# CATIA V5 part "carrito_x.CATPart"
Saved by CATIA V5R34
Part number: Part6
Bounding box of the stored display mesh (mm): x -30 to 30, y 0 to 70, z 0 to 11
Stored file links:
  C:\Users\Apolinar\Desktop\cnc\carrito_x.CATPart
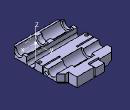
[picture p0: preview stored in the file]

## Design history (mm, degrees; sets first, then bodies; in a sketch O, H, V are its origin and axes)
AxisSystem1: origin (0, 0, 0), X (1, 0, 0), Y (0, 1, 0), Z (0, 0, 1)
Body1 (main body)
  Sketch1 on XY plane of AxisSystem1, origin (0, 0, 0), H (1, 0, 0), V (0, 1, 0)
    line L1 (-30, 70) -> (30, 70)
    line L2 (30, 70) -> (30, 0)
    line L3 (30, 0) -> (-30, 0)
    line L4 (-30, 0) -> (-30, 70)
    point P3 (30, 0)
    length L1 = 60
    length L2 = 70
    distance V L2 = 30
    horizontal: L1 H, L3 H
    vertical: L2 V, L4 V
    coincidence: P3 H
  Pad1: profile Sketch1, direction (0, 0, 1), length 11
  Sketch2 on end face of Pad1, origin (0, 0, 11), H (1, 0, 0), V (0, 1, 0)
    line L1 (-27, 18.35) -> (-3, 18.35)
    line L2 (-3, 18.35) -> (-3, 2.35)
    line L3 (-3, 2.35) -> (-27, 2.35)
    line L4 (-27, 2.35) -> (-27, 18.35)
    line L5 (3, 18.35) -> (27, 18.35)
    line L6 (27, 18.35) -> (27, 2.35)
    line L7 (27, 2.35) -> (3, 2.35)
    line L8 (3, 2.35) -> (3, 18.35)
    line L9 (-12, 58.35) -> (12, 58.35)
    line L10 (12, 58.35) -> (12, 42.35)
    line L11 (12, 42.35) -> (-12, 42.35)
    line L12 (-12, 42.35) -> (-12, 58.35)
    reference projected line E1 (-30, 70) -> (-30, 0) from edge [face of Pad1 from Sketch1.L4 | end face of Pad1]
    reference projected line E2 (30, 0) -> (30, 70) from edge [face of Pad1 from Sketch1.L2 | end face of Pad1]
    construction line L13 (-27, 10.35) -> (3, 10.35)
    point P13 (-27, 10.35)
    point P14 (3, 10.35)
    construction line L14 (-12, 50.35) -> (-4.1097, 50.35)
    point P15 (-12, 50.35)
    reference projected line E3 (-30, 0) -> (30, 0) from edge [face of Pad1 from Sketch1.L3 | end face of Pad1]
    axis line L15 (0, 52.893) -> (0, 58.35)
    point P17 (0, 58.35)
    length L9 = 24
    length L10 = 16
    length L4 = 16
    length L1 = 24
    length L5 = 24
    distance E1 L4 = 3
    distance L6 E2 = 3
    distance L13 L14 = 40
    distance L3 E3 = 2.35
    horizontal: L1 H, L3 H, L5 H, L7 H, L9 H, L11 H, L13 H, L14 H
    vertical: L2 V, L4 V, L6 V, L8 V, L10 V, L12 V, L15 V
    coincidence: L3 L7, P17 L9, L15 V
    midpoint: P15 L12, P13 L4, P14 L8, P17 L9
  Pocket1: profile Sketch2, direction (0, 0, -1), length 7.6
  Fillet1: radius 7.5, on edge [face of Pocket1 from Sketch2.L9 | end face of Pocket1]; edge [face of Pocket1 from Sketch2.L11 | end face of Pocket1]; edge [face of Pocket1 from Sketch2.L5 | end face of Pocket1]; edge [face of Pocket1 from Sketch2.L1 | end face of Pocket1]; edge [face of Pocket1 from Sketch2.L7 | end face of Pocket1]; edge [face of Pocket1 from Sketch2.L3 | end face of Pocket1]
  Sketch3 on face of Pad1 from Sketch1.L4, origin (-30, 0, 0), H (0, -1, 0), V (0, 0, 1)
    circle A1 centre (-49.85, 10.9) radius 5
    circle A2 centre (-9.85, 10.9) radius 5
    axis line L1 (-49.85, 10.9) -> (-9.85, 10.9)
    reference projected point E1 (-49.85, 10.9) from axis of face of Fillet1
    reference projected point E2 (-9.85, 10.9) from axis of face of Fillet1
    radius A1 = 5
    radius A2 = 5
    concentricity: A1 E1, A2 E2
  Pocket2: profile Sketch3, direction (1, 0, 0), through (limit type 3)
  Sketch4 on end face of Pad1, origin (0, 0, 11), H (1, 0, 0), V (0, 1, 0)
    circle A1 centre (-27.5, 32.851) radius 1.75
    point P1 (-27.5, 32.851)
    reference projected point E1 (-30, 44.851) from vertex [face of Pad1 from Sketch1.L4 | face of Pocket2 from Sketch3.A1 | end face of Pad1]
    circle A2 centre (27.5, 32.851) radius 1.75
    radius A1 = 1.75
    distance P1 V = 27.5
    distance E1 P1 V = 12
    symmetry: A1 A2 V
  Pocket3: profile Sketch4, direction (0, 0, -1), through (limit type 3)
  Sketch5 on end face of Pad1, origin (0, 0, 11), H (1, 0, 0), V (0, 1, 0)
    reference projected line E1 through (0, 9.85) direction (-1, 0) from axis of face of Fillet1
    reference projected line E2 through (0, 49.85) direction (-1, 0) from axis of face of Pocket2 from Sketch3.A1
    construction line L1 (30, 22.85) -> (30, 38.85)
    point P2 (30, 38.85)
    construction line L2 (21.2764, 30.85) -> (30, 30.85)
    point P4 (30, 30.85)
    reference projected line E3 (30, 0) -> (30, 70) from edge [face of Pad1 from Sketch1.L2 | end face of Pad1]
    axis line L3 (30, 38.85) -> (-20.2179, 38.85)
    point P5 (-20.2179, 38.85)
    point P6 (-20.2179, 22.85)
    point P7 (30, 22.85)
    construction line L4 (30, 22.85) -> (-20.2179, 22.85)
    point P8 (-30, 39.7)
    line L5 (-30, 39.7) -> (-10, 39.7)
    line L6 (-10, 39.7) -> (-10, 38.2)
    line L7 (-10, 38.2) -> (-30, 38.2)
    line L8 (-30, 38.2) -> (-30, 39.7)
    point P9 (-10, 39.7)
    point P10 (-10, 38.2)
    point P11 (-30, 38.2)
    reference projected line E4 (-30, 70) -> (-30, 0) from edge [face of Pad1 from Sketch1.L4 | end face of Pad1]
    reference projected line E5 through (0, 10.85) direction (1, 0) from axis of face of Fillet1
    point P12 (20.2179, 38.85)
    point P13 (30, 39.7)
    point P14 (10, 39.7)
    point P15 (10, 38.2)
    point P16 (30, 38.2)
    line L9 (30, 39.7) -> (10, 39.7)
    line L10 (10, 39.7) -> (10, 38.2)
    line L11 (10, 38.2) -> (30, 38.2)
    line L12 (30, 38.2) -> (30, 39.7)
    line L13 (-30, 29.5) -> (30, 29.5)
    line L14 (30, 29.5) -> (30, 19.5)
    line L15 (30, 19.5) -> (-30, 19.5)
    line L16 (-30, 19.5) -> (-30, 29.5)
    distance E1 E2 = 40 (reference)
    length L1 = 16
    length L8 = 1.5
    distance L7 L3 = 0.65
    length L7 = 20
    distance L2 E5 = 20
    length L14 = 10
    distance L15 H = 19.5
    vertical: L1 V, L6 V, L8 V, L14 V, L16 V
    horizontal: L2 H, L3 H, L5 H, L7 H, L13 H, L15 H
    midpoint: P4 L1
    coincidence: L1 E3, L8 E4, L16 E4, E3 L14
    symmetry: P5 P6 L2, P2 P7 L2, L3 L4 L2, P5 P12 V, P8 P13 V, P9 P14 V, P10 P15 V, P11 P16 V, L5 L9 V, L6 L10 V, L7 L11 V, L8 L12 V
  Pocket4: profile Sketch5, direction (0, 0, -1), length 8
  Plane1: type Angle, RefPlane ZX plane of AxisSystem1, Direction edge [ZX plane of AxisSystem1 | YZ plane of AxisSystem1], Angle 45
  Sketch6 on Plane1, origin (0, 0, 0), H (-0.7071, -0.7071, 0), V (0, 0, 1)
    circle A1 centre (-9.3589, 6) radius 1.5
    reference projected point E1 (-6.8589, 3) from vertex [face of Pocket4 from Sketch5.L5 | end face of Pocket4 | face of Pad1 from Sketch1.L4]
    reference projected line E2 (-6.8589, 11) -> (-6.8589, 3) from edge [face of Pad1 from Sketch1.L4 | face of Pocket4 from Sketch5.L5]
    radius A1 = 1.5
    distance A1 E1 V = 1.5
    distance A1 E2 = 1
  Pocket5: profile Sketch6, direction (-0.7071, 0.7071, 0), length 60, opposite side length -30
  Plane2: stored without definition
  DatumSurface1
  DatumSurface2
  Mirror1: of Pocket5, about YZ plane of AxisSystem1
  DatumCurve1 to DatumCurve3
  Sketch7 on start face of Pad1, origin (0, 0, 0), H (1, 0, 0), V (0, -1, 0)
    line L1 (-30, -65) -> (-11.5, -65)
    line L2 (-11.5, -65) -> (-11.5, -70)
    line L3 (-11.5, -70) -> (-30, -70)
    line L4 (-30, -70) -> (-30, -65)
    reference projected line E1 (30, -70) -> (-30, -70) from edge [start face of Pad1 | face of Pad1 from Sketch1.L1]
    line L5 (-1.5, -62.7) -> (0.8, -62.7)
    line L6 (0.8, -62.7) -> (0.8, -70)
    line L7 (0.8, -70) -> (-1.5, -70)
    line L8 (-1.5, -70) -> (-1.5, -62.7)
    reference projected line E2 (-1.5, -70) -> (-1.5, -62.7) from edge of DatumCurve1
    reference projected line E3 (-1.5, -62.7) -> (3.5, -62.7) from edge of DatumCurve2
    reference projected line E4 (0.8, -62.7) -> (0.8, -70) from edge of DatumCurve3
    line L9 (20.8, -60) -> (30, -60)
    line L10 (30, -60) -> (30, -70)
    line L11 (30, -70) -> (20.8, -70)
    line L12 (20.8, -70) -> (20.8, -60)
    reference projected line E5 (30, 0) -> (30, -70) from edge [start face of Pad1 | face of Pad1 from Sketch1.L2]
    reference projected line E6 (-30, -70) -> (-30, 0) from edge [start face of Pad1 | face of Pad1 from Sketch1.L4]
    length L4 = 5
    distance L6 L12 = 20
    length L10 = 10
    distance L2 L8 = 10
    horizontal: L1 H, L3 H, L5 H, L7 H, L9 H, L11 H
    vertical: L2 V, L4 V, L6 V, L8 V, L10 V, L12 V
    coincidence: L3 E1, L7 E1, L8 E2, L5 E3, L6 E4, L11 E1, L10 E5, L4 E6
  Pocket6: profile Sketch7, direction (0, 0, 1), through (limit type 6)
  Sketch8 on face of Pocket6 from Sketch7.L8, origin (-1.5, 0, 0), H (0, 1, 0), V (0, 0, 1)
    circle A1 centre (66.45, 4.55) radius 1.55
    reference projected line E1 (62.7, 0) -> (70, 0) from edge [start face of Pad1 | face of Pocket6 from Sketch7.L8]
    reference projected line E2 (70, 0) -> (70, 11) from edge [face of Pad1 from Sketch1.L1 | face of Pocket6 from Sketch7.L8]
    radius A1 = 1.55
    distance A1 E1 = 3
    distance A1 E2 = 2
  Pad2: profile Sketch8, direction (1, 0, 0), up to the existing solid (limit type 2)
  Sketch9 on face of Pocket6 from Sketch7.L8, origin (-1.5, 0, 0), H (0, 1, 0), V (0, 0, 1)
    line L1 (62.7, 11) -> (70, 11)
    line L2 (70, 11) -> (70, 9)
    line L3 (70, 9) -> (62.7, 9)
    line L4 (62.7, 9) -> (62.7, 11)
    reference projected line E1 (70, 11) -> (62.7, 11) from edge [end face of Pad1 | face of Pocket6 from Sketch7.L8]
    reference projected line E2 (62.7, 0) -> (62.7, 11) from edge [face of Pocket6 from Sketch7.L5 | face of Pocket6 from Sketch7.L8]
    reference projected line E3 (70, 0) -> (70, 11) from edge [face of Pad1 from Sketch1.L1 | face of Pocket6 from Sketch7.L8]
    length L4 = 2
    horizontal: L1 H, L3 H
    vertical: L2 V, L4 V
    coincidence: E1 L1, L4 E2, L2 E3
  Pocket7: profile Sketch9, direction (-1, 0, 0), length 10
  Chamfer1: length 5, angle 45, on edge [face of Pad1 from Sketch1.L4 | face of Pocket6 from Sketch7.L1]; edge [face of Pocket6 from Sketch7.L9 | face of Pad1 from Sketch1.L2]; edge [face of Pad1 from Sketch1.L3 | face of Pad1 from Sketch1.L4]; edge [face of Pad1 from Sketch1.L2 | face of Pad1 from Sketch1.L3]
  Fillet2: radius 3, on edge [face of Pocket4 from Sketch5.L13 | end face of Pocket4]; edge [face of Pocket4 from Sketch5.L15 | end face of Pocket4]
  Chamfer2: length 3, angle 45, on edge [start face of Pad1 | face of Pad1 from Sketch1.L3]; edge [start face of Pad1 | face of Pad1 from Sketch1.L4]; edge [start face of Pad1 | face of Pad1 from Sketch1.L2]; edge [start face of Pad1 | face of Chamfer1] (x4)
